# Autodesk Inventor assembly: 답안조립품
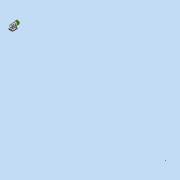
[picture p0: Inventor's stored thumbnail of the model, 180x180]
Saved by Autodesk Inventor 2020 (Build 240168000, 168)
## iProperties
Created: 2021-10
Part Number: 답안조립품
Document SubType Name: Assembly
Designer: user
Author: user
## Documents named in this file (12)
- C:\Users\user\Desktop\711007V1004\답안조립품.iam
- C:\Users\user\Desktop\711007V1004\V벨트풀리.ipt
- C:\Users\user\Desktop\711007V1004\멈춤나사 M3.ipt
- C:\Users\user\Desktop\711007V1004\베어링 6004.ipt
- C:\Users\user\Desktop\711007V1004\베어링 51202.ipt
- C:\Users\user\Desktop\711007V1004\본체.ipt
- C:\Users\user\Desktop\711007V1004\볼트 M4.ipt
- C:\Users\user\Desktop\711007V1004\어댑터슬리브.ipt
- C:\Users\user\Desktop\711007V1004\오일 실 20x35x7.ipt
- C:\Users\user\Desktop\711007V1004\축.ipt
- C:\Users\user\Desktop\711007V1004\커버.ipt
- C:\Users\user\Desktop\711007V1004\키 5x5.ipt
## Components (1 placed, 1 different names)
1. V벨트풀리:1
